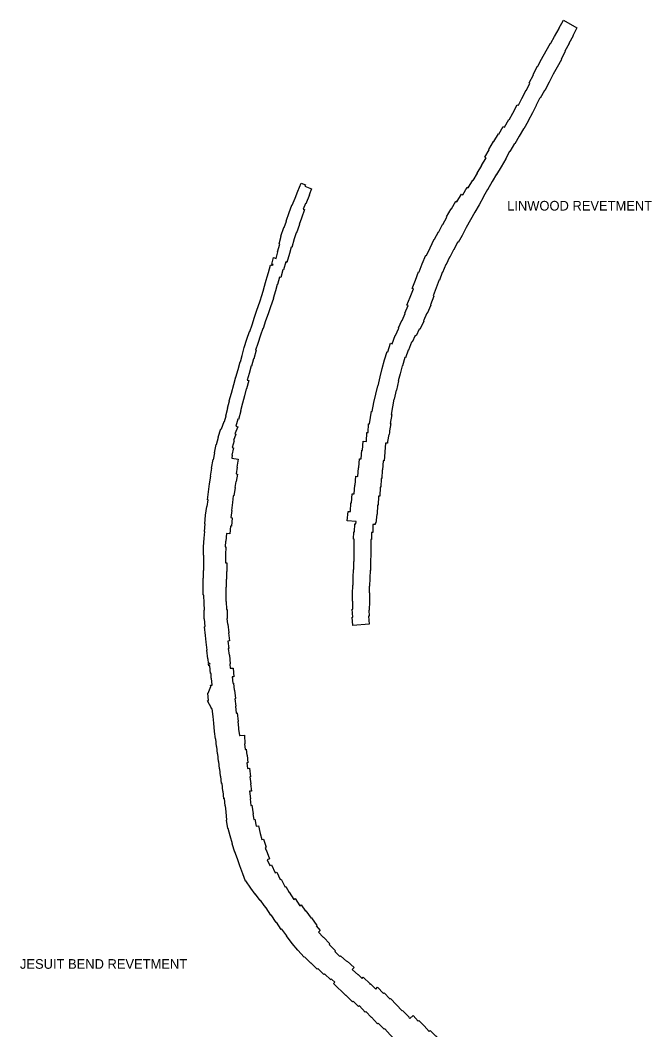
# Model space of a CAD drawing. Extents: x 2650582 to 3923188, y 277893 to 989177.
# Drawn here: x 3691960 to 3702423, y 455556 to 472280 of the extents above; entities that cross this region are included whole.
import ezdxf

# ---------------------------------------------------------------- set-up
doc = ezdxf.new("R2010")
doc.units = 0
doc.layers.add('Level 3', color=7, linetype='Continuous')

msp = doc.modelspace()

# ---------------------------------------------------------------- linework, layer by layer
at = {"layer": 'Level 3'}
msp.add_line((3697152, 456324), (3697172, 456345), dxfattribs=at)
for points in [[(3699463, 469627), (3699533, 469745), (3699530, 469746), (3699605, 469873), (3699603, 469875), (3699678, 469999), (3699659, 470012), (3699730, 470134), (3699725, 470137), (3699802, 470273), (3699806, 470271), (3699881, 470400), (3699890, 470394), (3699963, 470518), (3699981, 470508), (3700055, 470633), (3700060, 470630), (3700122, 470741), (3700119, 470743), (3700195, 470881), (3700213, 470872), (3700270, 470984), (3700268, 470985), (3700341, 471124), (3700345, 471122), (3700405, 471238), (3700392, 471245), (3700461, 471377), (3700457, 471380), (3700529, 471521), (3700536, 471518), (3700598, 471635), (3700596, 471637), (3700671, 471772), (3700743, 471902), (3700750, 471898), (3700814, 472011), (3700812, 472013), (3700886, 472142), (3700882, 472144), (3700958, 472280), (3701184, 472154)], [(3701184, 472154), (3701114, 472024), (3701120, 472020), (3701049, 471895), (3701052, 471893), (3700985, 471767), (3700990, 471764), (3700921, 471635), (3700928, 471631), (3700856, 471502), (3700790, 471384), (3700722, 471253), (3700650, 471115), (3700644, 471117), (3700575, 470990), (3700567, 470994), (3700506, 470872), (3700510, 470870), (3700447, 470746), (3700448, 470745), (3700373, 470612), (3700376, 470610), (3700304, 470480), (3700300, 470482), (3700227, 470358), (3700153, 470234), (3700148, 470237), (3700071, 470104), (3700068, 470106), (3700003, 469987), (3700007, 469985), (3699929, 469851), (3699925, 469853), (3699853, 469726), (3699849, 469728), (3699781, 469608), (3699703, 469473)], [(3698179, 467056), (3698230, 467181), (3698226, 467182), (3698282, 467305), (3698285, 467304), (3698339, 467424), (3698330, 467428), (3698385, 467553), (3698367, 467561), (3698421, 467692), (3698418, 467693), (3698473, 467833), (3698456, 467838), (3698508, 467972), (3698506, 467973), (3698560, 468113), (3698569, 468110), (3698620, 468243), (3698617, 468243), (3698681, 468390), (3698693, 468384), (3698749, 468511), (3698817, 468654), (3698823, 468652), (3698889, 468777), (3698893, 468775), (3698956, 468897), (3698960, 468894), (3699030, 469020), (3699024, 469023), (3699100, 469158), (3699105, 469156), (3699177, 469280), (3699195, 469271), (3699269, 469397), (3699292, 469386), (3699365, 469513), (3699381, 469504), (3699456, 469631), (3699463, 469627)], [(3695994, 467834), (3696034, 467975), (3696036, 467975), (3696051, 468027), (3696071, 468101), (3696075, 468100), (3696109, 468223), (3696121, 468220), (3696124, 468229), (3696147, 468223), (3696149, 468231), (3696126, 468237), (3696158, 468347), (3696198, 468335), (3696228, 468442), (3696224, 468443), (3696262, 468573), (3696248, 468577), (3696284, 468703), (3696279, 468705), (3696328, 468846), (3696331, 468844), (3696369, 468953), (3696368, 468953), (3696416, 469093), (3696418, 469093), (3696460, 469215), (3696464, 469214), (3696513, 469333), (3696514, 469333), (3696561, 469448), (3696559, 469448), (3696617, 469583), (3696684, 469555), (3696675, 469533), (3696786, 469486), (3696745, 469390), (3696751, 469387), (3696691, 469240), (3696687, 469242), (3696650, 469150), (3696670, 469143), (3696621, 469001), (3696618, 469002), (3696582, 468898), (3696585, 468897), (3696536, 468756), (3696530, 468758), (3696496, 468661), (3696499, 468660), (3696458, 468517), (3696449, 468519), (3696419, 468416), (3696421, 468416), (3696379, 468269), (3696360, 468275), (3696322, 468144), (3696311, 468147), (3696276, 468017), (3696255, 468023), (3696221, 467900)], [(3699703, 469473), (3699701, 469474), (3699633, 469358), (3699636, 469356), (3699562, 469224), (3699490, 469101), (3699419, 468974), (3699346, 468845), (3699280, 468716), (3699213, 468600), (3699207, 468602), (3699141, 468474), (3699136, 468476), (3699079, 468355), (3699073, 468357), (3699018, 468232), (3699012, 468234), (3698956, 468099), (3698953, 468100), (3698904, 467974), (3698899, 467977), (3698850, 467847), (3698853, 467846), (3698802, 467712), (3698813, 467708), (3698756, 467563), (3698760, 467561), (3698703, 467423), (3698698, 467425), (3698641, 467298), (3698644, 467297), (3698579, 467158), (3698569, 467163), (3698520, 467052), (3698505, 467058)], [(3695211, 465253), (3695244, 465373), (3695237, 465376), (3695286, 465513), (3695292, 465511), (3695338, 465632), (3695343, 465631), (3695372, 465724), (3695364, 465726), (3695399, 465852), (3695395, 465853), (3695428, 465976), (3695424, 465977), (3695459, 466103), (3695459, 466103), (3695497, 466243), (3695498, 466243), (3695531, 466370), (3695534, 466369), (3695568, 466494), (3695571, 466493), (3695606, 466620), (3695609, 466619), (3695638, 466724), (3695636, 466725), (3695672, 466856), (3695670, 466856), (3695715, 466995), (3695715, 466995), (3695759, 467125), (3695763, 467123), (3695803, 467235), (3695800, 467235), (3695842, 467359), (3695841, 467360), (3695881, 467479), (3695927, 467617), (3695928, 467617), (3695967, 467734), (3695969, 467734), (3695997, 467833), (3695994, 467834)], [(3696221, 467900), (3696217, 467901), (3696188, 467797), (3696189, 467796), (3696153, 467672), (3696154, 467672), (3696108, 467534), (3696108, 467534), (3696068, 467416), (3696066, 467417), (3696026, 467298), (3696025, 467298), (3695983, 467174), (3695981, 467175), (3695941, 467063), (3695942, 467063), (3695895, 466925), (3695895, 466925), (3695859, 466815), (3695867, 466812), (3695828, 466672), (3695825, 466673), (3695792, 466552), (3695788, 466553), (3695754, 466429), (3695751, 466430), (3695721, 466320), (3695745, 466313), (3695708, 466173), (3695706, 466174), (3695674, 466059), (3695674, 466059), (3695641, 465936), (3695645, 465935), (3695610, 465809), (3695614, 465808), (3695576, 465668), (3695566, 465671), (3695531, 465558), (3695563, 465546), (3695518, 465429), (3695534, 465423), (3695496, 465317), (3695503, 465315), (3695472, 465203), (3695491, 465199)], [(3697745, 465594), (3697780, 465802), (3697792, 465801), (3697819, 465946), (3697821, 465945), (3697850, 466085), (3697854, 466085), (3697887, 466226), (3697891, 466225), (3697921, 466372), (3697956, 466513), (3697959, 466513), (3697993, 466653), (3697997, 466652), (3698039, 466792), (3698051, 466788), (3698094, 466930), (3698124, 466921), (3698174, 467058), (3698179, 467056)], [(3698505, 467058), (3698452, 466945), (3698441, 466949), (3698395, 466814), (3698386, 466817), (3698344, 466688), (3698332, 466691), (3698293, 466553), (3698286, 466555), (3698256, 466422), (3698253, 466423), (3698224, 466305), (3698226, 466304), (3698193, 466151), (3698188, 466151), (3698155, 466004), (3698152, 466004), (3698126, 465877), (3698130, 465876), (3698108, 465748), (3698114, 465748), (3698090, 465602), (3698098, 465601), (3698078, 465479)], [(3697379, 463990), (3697392, 464144), (3697429, 464142), (3697440, 464286), (3697449, 464286), (3697460, 464436), (3697494, 464433), (3697504, 464578), (3697510, 464577), (3697520, 464725), (3697551, 464724), (3697564, 464868), (3697570, 464869), (3697580, 465017), (3697609, 465016), (3697619, 465159), (3697628, 465159), (3697639, 465307), (3697698, 465304), (3697705, 465450), (3697723, 465450), (3697731, 465595), (3697745, 465594)], [(3698078, 465479), (3698076, 465455), (3698077, 465454), (3698076, 465448), (3698074, 465417), (3698069, 465417), (3698044, 465301), (3698042, 465272), (3698014, 465273), (3697988, 464981), (3697975, 464981), (3697964, 464831), (3697959, 464831), (3697950, 464686), (3697942, 464686), (3697932, 464544), (3697925, 464544), (3697916, 464394), (3697898, 464395), (3697889, 464246), (3697881, 464246), (3697872, 464098), (3697867, 464098), (3697852, 463950), (3697841, 463951)], [(3695010, 462362), (3695008, 462509), (3695012, 462509), (3695010, 462623), (3695005, 462623), (3695003, 462758), (3694992, 462759), (3694993, 462892), (3694990, 462892), (3694991, 463038), (3694995, 463038), (3694996, 463167), (3695000, 463167), (3695001, 463283), (3695000, 463283), (3695001, 463421), (3694994, 463421), (3694999, 463554), (3694997, 463554), (3695008, 463698), (3695009, 463698), (3695018, 463808), (3695011, 463809), (3695022, 463935), (3695018, 463935), (3695031, 464081), (3695029, 464081), (3695052, 464224), (3695056, 464223), (3695073, 464335), (3695061, 464337), (3695082, 464467), (3695077, 464468), (3695098, 464599), (3695097, 464599), (3695118, 464728), (3695114, 464728), (3695134, 464858), (3695131, 464859), (3695156, 465001), (3695163, 465000), (3695183, 465111), (3695180, 465112), (3695207, 465254), (3695211, 465253)], [(3695491, 465199), (3695468, 465077), (3695473, 465076), (3695464, 465024), (3695569, 465008), (3695548, 464879), (3695555, 464878), (3695537, 464766), (3695559, 464762), (3695539, 464640), (3695534, 464641), (3695518, 464538), (3695522, 464537), (3695500, 464399), (3695489, 464401), (3695476, 464291), (3695477, 464290), (3695461, 464161), (3695466, 464161), (3695451, 464041), (3695471, 464039), (3695459, 463900), (3695445, 463901), (3695434, 463772), (3695377, 463777), (3695367, 463651), (3695361, 463651), (3695354, 463554), (3695364, 463554), (3695359, 463426), (3695362, 463426), (3695361, 463294), (3695383, 463294), (3695383, 463148), (3695379, 463148), (3695378, 463019), (3695374, 463019), (3695373, 462889), (3695369, 462889), (3695368, 462756), (3695366, 462756), (3695368, 462649), (3695373, 462649), (3695376, 462516), (3695388, 462516), (3695391, 462369), (3695385, 462369), (3695392, 462278)], [(3697469, 462251), (3697457, 462390), (3697472, 462391), (3697460, 462523), (3697468, 462524), (3697470, 462655), (3697466, 462655), (3697466, 462779), (3697469, 462919), (3697474, 462919), (3697476, 463051), (3697481, 463183), (3697485, 463183), (3697487, 463313), (3697492, 463313), (3697492, 463437), (3697494, 463577), (3697495, 463682), (3697484, 463682), (3697487, 463806), (3697500, 463807), (3697503, 463938), (3697522, 463938), (3697523, 463978), (3697379, 463990)], [(3697841, 463951), (3697841, 463924), (3697802, 463924), (3697799, 463792), (3697779, 463793), (3697777, 463677), (3697769, 463677), (3697769, 463571), (3697767, 463439), (3697764, 463307), (3697761, 463167), (3697755, 463168), (3697752, 463038), (3697746, 462906), (3697742, 462906), (3697740, 462796), (3697748, 462796), (3697745, 462656), (3697745, 462650), (3697742, 462510), (3697734, 462510), (3697743, 462409), (3697728, 462407), (3697740, 462274), (3697469, 462251)], [(3695121, 461456), (3695112, 461456), (3695100, 461586), (3695085, 461584), (3695082, 461615), (3695105, 461617), (3695104, 461625), (3695082, 461622), (3695074, 461702), (3695066, 461701), (3695050, 461846), (3695056, 461847), (3695041, 461977), (3695043, 461977), (3695031, 462088), (3695029, 462088), (3695012, 462234), (3695023, 462235), (3695013, 462362), (3695010, 462362)], [(3695392, 462278), (3695397, 462278), (3695414, 462132), (3695411, 462132), (3695427, 461999), (3695402, 461996), (3695417, 461872), (3695406, 461871), (3695419, 461761), (3695426, 461761), (3695439, 461616), (3695431, 461615), (3695437, 461544)], [(3695344, 459386), (3695336, 459385), (3695322, 459511), (3695316, 459510), (3695303, 459638), (3695295, 459637), (3695282, 459759), (3695278, 459759), (3695265, 459880), (3695263, 459880), (3695250, 460003), (3695245, 460003), (3695232, 460126), (3695231, 460126), (3695218, 460249), (3695213, 460248), (3695199, 460376), (3695194, 460376), (3695181, 460497), (3695180, 460496), (3695165, 460638), (3695168, 460638), (3695157, 460747), (3695154, 460747), (3695140, 460875), (3695129, 460873), (3695128, 460885), (3695064, 461004), (3695080, 461013), (3695066, 461133), (3695072, 461133), (3695117, 461245), (3695115, 461263), (3695138, 461265), (3695128, 461382), (3695126, 461382), (3695121, 461456)], [(3695437, 461544), (3695488, 461547), (3695497, 461405), (3695474, 461403), (3695483, 461299), (3695491, 461300), (3695502, 461183), (3695512, 461184), (3695528, 461043), (3695517, 461041), (3695531, 460920), (3695524, 460919), (3695538, 460804), (3695553, 460806), (3695568, 460664), (3695565, 460664), (3695576, 460560), (3695577, 460560), (3695579, 460536), (3695591, 460432), (3695596, 460432), (3695596, 460430), (3695673, 460435), (3695683, 460296), (3695677, 460295), (3695684, 460202), (3695706, 460203), (3695713, 460103), (3695721, 460104), (3695733, 459980), (3695715, 459978), (3695724, 459885), (3695759, 459888), (3695774, 459749), (3695763, 459748), (3695780, 459631), (3695776, 459630), (3695792, 459511)], [(3695792, 459511), (3695757, 459507), (3695775, 459383), (3695767, 459382), (3695783, 459273), (3695798, 459275), (3695818, 459136), (3695814, 459136), (3695828, 459040), (3695848, 459044), (3695871, 458927), (3695905, 458935)], [(3696034, 457574), (3696000, 457613), (3696003, 457616), (3695938, 457701), (3695937, 457700), (3695857, 457804), (3695852, 457801), (3695779, 457904), (3695778, 457903), (3695697, 458022), (3695692, 458020), (3695648, 458140), (3695648, 458140), (3695600, 458272), (3695601, 458272), (3695559, 458387), (3695560, 458388), (3695518, 458502), (3695516, 458501), (3695473, 458636), (3695476, 458637), (3695436, 458770), (3695438, 458770), (3695405, 458890), (3695402, 458889), (3695377, 459028), (3695385, 459030), (3695370, 459166), (3695371, 459166), (3695360, 459264), (3695357, 459264), (3695344, 459386)], [(3695905, 458935), (3695934, 458807), (3695961, 458707), (3695991, 458716), (3696032, 458582), (3696017, 458578), (3696031, 458535), (3696034, 458536), (3696091, 458389), (3696052, 458374), (3696096, 458276), (3696123, 458289), (3696185, 458158), (3696210, 458170), (3696269, 458045), (3696281, 458052), (3696348, 457921), (3696363, 457930), (3696417, 457833)], [(3696417, 457833), (3696418, 457834), (3696493, 457716), (3696515, 457731), (3696592, 457611), (3696617, 457627), (3696685, 457522), (3696691, 457527), (3696781, 457408), (3696784, 457410), (3696875, 457286), (3696862, 457276), (3696931, 457200)], [(3696559, 456876), (3696560, 456877), (3696463, 456985), (3696465, 456987), (3696374, 457111), (3696375, 457113), (3696292, 457225), (3696284, 457219), (3696207, 457338), (3696200, 457333), (3696119, 457458), (3696111, 457453), (3696034, 457574)], [(3696931, 457200), (3696903, 457175), (3696981, 457089), (3696984, 457091), (3697092, 456983), (3697078, 456968), (3697181, 456866), (3697170, 456855), (3697254, 456771), (3697266, 456784), (3697373, 456685), (3697379, 456692), (3697491, 456588), (3697462, 456557)], [(3697172, 456345), (3697124, 456388), (3697123, 456387), (3697113, 456396), (3697104, 456386), (3696999, 456484), (3696988, 456474), (3696889, 456573), (3696879, 456563), (3696776, 456666), (3696773, 456662), (3696668, 456766), (3696663, 456761), (3696559, 456876)], [(3697462, 456557), (3697467, 456552), (3697558, 456467), (3697561, 456470), (3697627, 456408), (3697644, 456427), (3697757, 456318), (3697752, 456311), (3697755, 456309), (3697762, 456316), (3697851, 456232), (3697881, 456262), (3697978, 456159), (3697990, 456170), (3698085, 456068), (3698092, 456076), (3698288, 455872), (3698292, 455877), (3698401, 455764), (3698398, 455761), (3698417, 455743), (3698468, 455791)], [(3698199, 455369), (3698091, 455474), (3698091, 455475), (3697998, 455574), (3697989, 455565), (3697918, 455638), (3697889, 455665), (3697881, 455657), (3697781, 455764), (3697778, 455762), (3697687, 455860), (3697677, 455851), (3697581, 455952), (3697567, 455940), (3697478, 456030), (3697467, 456021), (3697355, 456128), (3697354, 456127), (3697152, 456324)], [(3698468, 455791), (3698553, 455700), (3698565, 455711), (3698650, 455621), (3698651, 455622), (3698737, 455530), (3698754, 455546), (3698840, 455454), (3698843, 455457), (3698923, 455373), (3699013, 455284), (3699020, 455290), (3699118, 455192), (3699100, 455173), (3699274, 454996)]]:
    msp.add_lwpolyline(points, dxfattribs=at)

# ---------------------------------------------------------------- texts
for s, p in [('LINWOOD REVETMENT', (3700027, 469127)), ('JESUIT BEND REVETMENT', (3691956, 456567))]:
    msp.add_text(s, height=160, dxfattribs=at).set_placement(p)

doc.saveas('drawing.dxf')
